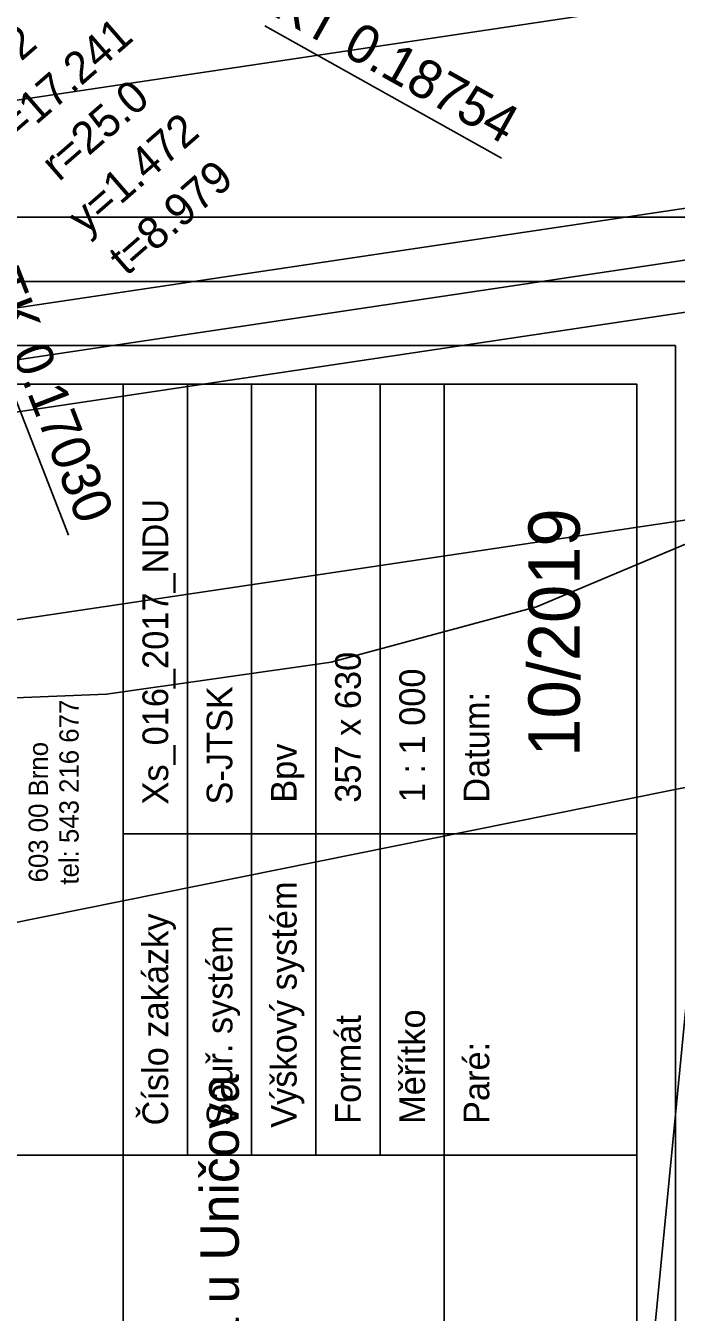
# Model space of a CAD drawing. Extents: x -555887 to -552101, y -1100251 to -1096546.
# Drawn here: x -554017.2 to -553966.6, y -1096851 to -1096750.8 of the extents above; entities that cross this region are included whole.
import ezdxf

# ---------------------------------------------------------------- set-up
doc = ezdxf.new("R2010")
doc.units = 0
for name, color, linetype in [('07_ELEKTRO', 7, 'Continuous'), ('07_OCH_P A POPISY TI', 7, 'Continuous'), ('07_PLYNOVOD', 7, 'Continuous'), ('ram_VC6', 7, 'Continuous'), ('vrstevnice', 7, 'Continuous'), ('ZSST', 7, 'Continuous'), ('zájem', 7, 'Continuous')]:
    doc.layers.add(name, color=color, linetype=linetype)

msp = doc.modelspace()

# ---------------------------------------------------------------- linework, layer by layer
for p, q in [((-553998.61, -1096750.84), (-553980.2, -1096761.13)), ((-554021.56, -1096770.81), (-554013.9, -1096790.47))]:
    msp.add_line(p, q)
at = {"layer": '07_ELEKTRO'}
msp.add_lwpolyline([(-554384.81, -1096800.66), (-554151.09, -1096831.04), (-554101.03, -1096837.49), (-554021.9, -1096821.39), (-553942.87, -1096805.47), (-553853.14, -1096787.39)], dxfattribs=at)
at = {"layer": '07_OCH_P A POPISY TI'}
msp.add_lwpolyline([(-554130.52, -1096773.53), (-554061.92, -1096763.17), (-553969.23, -1096749.35), (-553879.89, -1096736.04), (-553864.66, -1096733.65), (-553882.5, -1096776.87), (-553963.33, -1096788.91), (-554055.98, -1096802.73), (-554135.08, -1096814.67)], dxfattribs=at)
msp.add_lwpolyline([(-554152.6, -1096784.88), (-554208.41, -1096768.47), (-554202.28, -1096761.93), (-554150.14, -1096777.26), (-554149.47, -1096777.3), (-554148.05, -1096777.98), (-554147.52, -1096778.57), (-554137.26, -1096789.93), (-554136.6, -1096790.62), (-554059.54, -1096778.99), (-553966.87, -1096765.17), (-553877.47, -1096751.86), (-553871.81, -1096750.97), (-553875.38, -1096759.63), (-553876.26, -1096759.76), (-553965.69, -1096773.09), (-554058.36, -1096786.91), (-554137.46, -1096798.84), (-554137.94, -1096798.92), (-554138.9, -1096798.83), (-554139.81, -1096798.52), (-554140.63, -1096798), (-554140.96, -1096797.65), (-554143.12, -1096795.37)], close=True, dxfattribs=at)
at = {"layer": '07_PLYNOVOD'}
msp.add_lwpolyline([(-553873.6, -1096755.3), (-553876.86, -1096755.81), (-553966.28, -1096769.13), (-554058.95, -1096782.95), (-554138.06, -1096794.89), (-554140.19, -1096792.65), (-554150.49, -1096781.25), (-554150.83, -1096781.23), (-554205.35, -1096765.2)], dxfattribs=at)
at = {"layer": 'ram_VC6'}
for p, q in [((-554009.64, -1096958.72), (-554009.64, -1096778.72)), ((-554004.64, -1096838.72), (-554004.64, -1096778.72)), ((-553999.64, -1096838.72), (-553999.64, -1096778.72)), ((-553999.64, -1096838.72), (-553999.64, -1096778.72)), ((-553994.64, -1096838.72), (-553994.64, -1096778.72)), ((-553994.64, -1096838.72), (-553994.64, -1096778.72)), ((-553989.64, -1096838.72), (-553989.64, -1096778.72)), ((-553984.64, -1096958.72), (-553984.64, -1096778.72)), ((-554009.64, -1096813.72), (-553969.64, -1096813.72)), ((-554029.64, -1096838.72), (-553969.64, -1096838.72))]:
    msp.add_line(p, q, dxfattribs=at)
for points in [[(-553956.64, -1096765.72), (-554313.64, -1096765.72), (-554313.64, -1097395.72), (-553956.64, -1097395.72)], [(-553961.64, -1096770.72), (-554308.64, -1096770.72), (-554308.64, -1097390.72), (-553961.64, -1097390.72)], [(-554032.64, -1096961.72), (-554032.64, -1096775.72), (-553966.64, -1096775.72), (-553966.64, -1096961.72)], [(-554029.64, -1096958.72), (-554029.64, -1096778.72), (-553969.64, -1096778.72), (-553969.64, -1096958.72)]]:
    msp.add_lwpolyline(points, close=True, dxfattribs=at)
for points in [[(-553956.64, -1096765.72), (-554313.64, -1096765.72), (-554313.64, -1097395.72), (-553956.64, -1097395.72), (-553956.64, -1096765.72)], [(-553956.64, -1096765.72), (-554313.64, -1096765.72), (-554313.64, -1097395.72), (-553956.64, -1097395.72), (-553956.64, -1096765.72)], [(-553961.64, -1097390.72), (-554308.64, -1097390.72), (-554308.64, -1096770.72), (-553961.64, -1096770.72), (-553961.64, -1097390.72)], [(-553961.64, -1097185.72), (-553961.64, -1097390.72), (-554308.64, -1097390.72), (-554308.64, -1096770.72), (-553961.64, -1096770.72), (-553961.64, -1096975.72), (-553961.64, -1097185.72)]]:
    msp.add_lwpolyline(points, dxfattribs=at)
at = {"layer": 'vrstevnice'}
msp.add_lwpolyline([(-554109.6, -1096807.35), (-554060.65, -1096804.85), (-554010.94, -1096802.86), (-553993.46, -1096800.36), (-553977.47, -1096796.05), (-553960.12, -1096788.77), (-553945.29, -1096782.24), (-553937.24, -1096775.46), (-553928.19, -1096763.91), (-553924.17, -1096755.88), (-553916.12, -1096742.07), (-553910.34, -1096729.02), (-553897.27, -1096712.7)], dxfattribs=at)
at = {"layer": 'ZSST'}
msp.add_lwpolyline([(-554226.18, -1096821.12), (-554151.09, -1096831.04), (-554101.03, -1096837.49), (-554021.9, -1096821.39), (-553942.87, -1096805.47)], dxfattribs=at)
at = {"layer": 'zájem'}
for points in [[(-553972.09, -1096891.8), (-553954.59, -1096711.31), (-553940.56, -1096702.53), (-553941.94, -1096699.09), (-553940.67, -1096693.09), (-553930.01, -1096689.96), (-553913.04, -1096676.61), (-553907.22, -1096657.99), (-553900.18, -1096624.72), (-553904.1, -1096616.61), (-553906.1, -1096627.16), (-553925.07, -1096615.99), (-553949.77, -1096614.6), (-553980.12, -1096613.41), (-553985.27, -1096613.98), (-553991.23, -1096625.03), (-554008.75, -1096645.87), (-554021.42, -1096660.84), (-554089.18, -1096729.49), (-554110.69, -1096747.36)], [(-554110.69, -1096747.36), (-554089.18, -1096729.49), (-554021.42, -1096660.84), (-554008.75, -1096645.87), (-553991.23, -1096625.03), (-553985.27, -1096613.98), (-553980.12, -1096613.41), (-553949.77, -1096614.6), (-553925.07, -1096615.99), (-553906.1, -1096627.16), (-553904.1, -1096616.61), (-553900.18, -1096624.72), (-553907.22, -1096657.99), (-553913.04, -1096676.61), (-553930.01, -1096689.96), (-553940.67, -1096693.09), (-553941.94, -1096699.09), (-553940.56, -1096702.53), (-553954.59, -1096711.31), (-553972.09, -1096891.8)]]:
    msp.add_lwpolyline(points, dxfattribs=at)

# ---------------------------------------------------------------- texts
for s, height, rotation, p in [('KT 0.18754', 3, 330.7904, (-553998.12, -1096749.97)), ('L=17.241', 2.5, 41.0338, (-554019.31, -1096761.1)), ('2', 2.5, 41.0338, (-554017.59, -1096753.64)), ('r=25.0', 2.5, 41.0338, (-554014.65, -1096763.01)), ('y=1.472', 2.5, 41.0338, (-554012.6, -1096767.19)), ('t=8.979', 2.5, 41.0338, (-554009.38, -1096770.36)), ('TK 0.17030', 3, 291.2773, (-554020.62, -1096770.45))]:
    msp.add_text(s, height=height, rotation=rotation).set_placement(p)
at = {"layer": 'ram_VC6'}
for s, height, p in [('Xs_016_2017_NDU', 2, (-554006.14, -1096811.44)), ('10/2019', 4, (-553974.09, -1096807.72)), ('357 x 630', 2, (-553991.14, -1096811.3)), ('1 : 1 000', 2, (-553986.14, -1096811.26)), ('S-JTSK', 2, (-554001.14, -1096811.44)), ('tel: 543 216 677', 1.5, (-554013.11, -1096817.67)), ('Datum:', 2, (-553981.14, -1096811.3)), ('603 00 Brno', 1.5, (-554015.5, -1096817.5)), ('Bpv', 2, (-553996.14, -1096811.3)), ('Výškový systém', 2, (-553996.14, -1096836.6)), ('Číslo zakázky', 2, (-554006.14, -1096836.42)), ('Souř. systém', 2, (-554001.14, -1096836.44)), ('Formát', 2, (-553991.14, -1096836.3)), ('Měřítko', 2, (-553986.14, -1096836.3)), ('Paré:', 2, (-553981.14, -1096836.3)), ('Komplexní pozemkové úpravy v  k.ú. Nová Dědina u Uničova', 3, (-554000.64, -1096941.25))]:
    msp.add_text(s, height=height, rotation=90, dxfattribs=at).set_placement(p)

doc.saveas('drawing.dxf')
